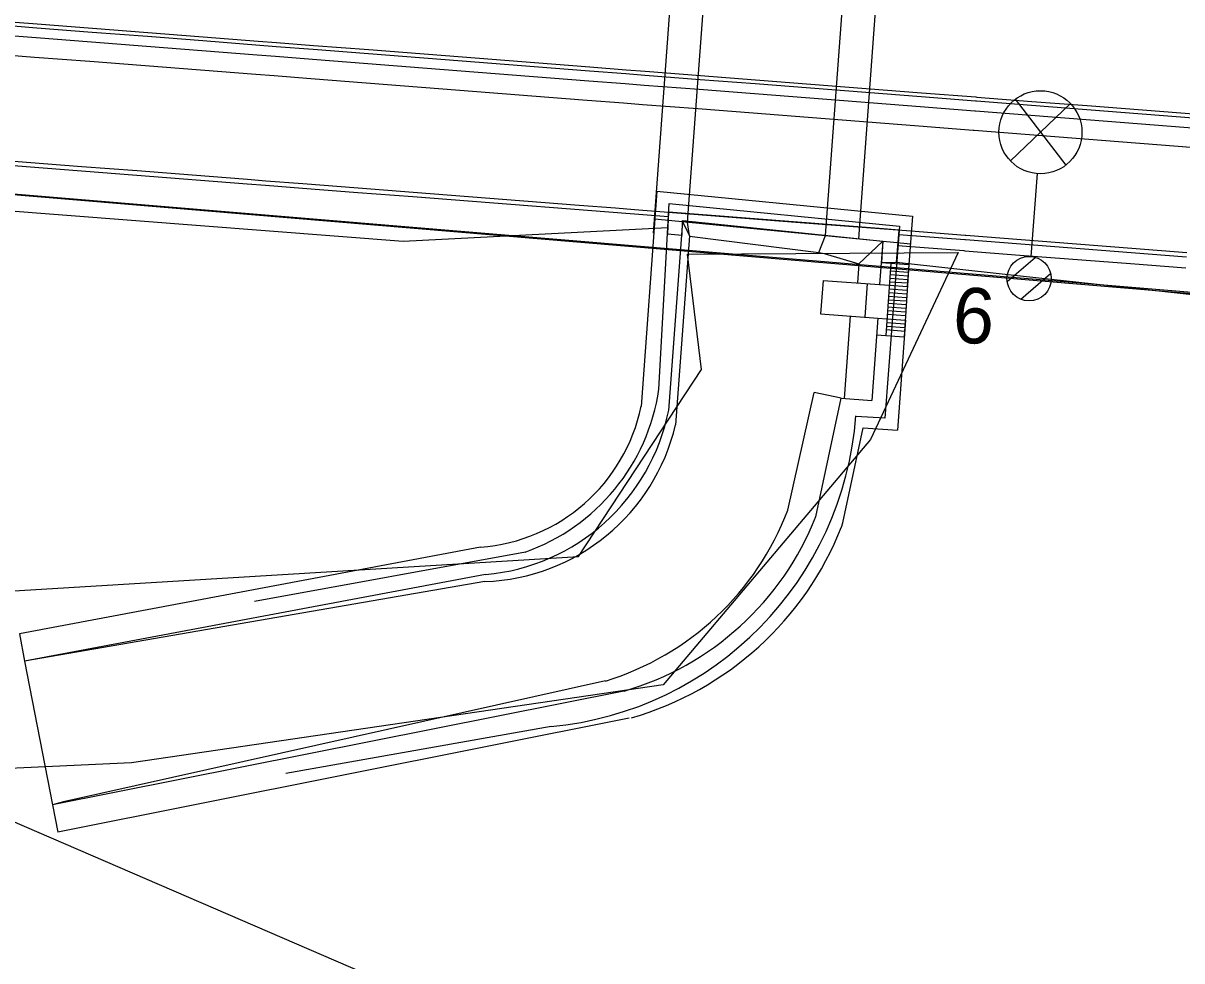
# Model space of a CAD drawing. Extents: x -670359 to -668019, y -978807 to -976674.
# Drawn here: x -669486.95 to -669466.04, y -977163.16 to -977146.25 of the extents above; entities that cross this region are included whole.
import ezdxf

# ---------------------------------------------------------------- set-up
doc = ezdxf.new("R2010")
doc.units = 0
for name, color, linetype in [('SO 01-20-01', 7, 'Continuous'), ('SO 01-86-01', 7, 'Continuous'), ('SO 11-12-01', 7, 'Continuous'), ('Vnitřní kresba', 7, 'Continuous')]:
    doc.layers.add(name, color=color, linetype=linetype)

# ---------------------------------------------------------------- blocks, each defined once
blk = doc.blocks.new('POINT_DISPLAY')
blk.add_line((0, 0), (0, 0))

msp = doc.modelspace()

# ---------------------------------------------------------------- linework, layer by layer
at = {"layer": 'SO 01-20-01'}
for p, q in [((-669475.576, -977150.04), (-669474.546, -977136.022)), ((-669474.959, -977149.839), (-669473.947, -977136.066)), ((-669472.47, -977150.083), (-669471.452, -977136.221)), ((-669471.836, -977149.643), (-669470.854, -977136.265)), ((-669475.513, -977149.282), (-669475.799, -977153.166)), ((-669475.513, -977149.282), (-669470.904, -977149.735)), ((-669475.478, -977152.855), (-669475.294, -977149.507)), ((-669475.294, -977149.507), (-669471.139, -977149.914)), ((-669471.873, -977150.142), (-669471.836, -977149.643)), ((-669475.55, -977149.781), (-669470.941, -977150.233)), ((-669475.051, -977149.83), (-669475.302, -977153.236)), ((-669475.051, -977149.83), (-669474.928, -977150.089)), ((-669474.928, -977150.089), (-669474.959, -977149.839)), ((-669471.139, -977149.914), (-669471.404, -977153.375)), ((-669470.904, -977149.735), (-669470.998, -977151.003)), ((-669474.928, -977150.089), (-669475.179, -977153.495)), ((-669474.928, -977150.092), (-669472.589, -977150.39)), ((-669472.589, -977150.39), (-669472.47, -977150.083)), ((-669471.87, -977150.593), (-669471.439, -977150.187)), ((-669471.439, -977150.187), (-669471.496, -977150.966)), ((-669472.589, -977150.39), (-669472.494, -977150.405)), ((-669472.494, -977150.405), (-669471.87, -977150.593)), ((-669471.87, -977150.593), (-669471.895, -977150.937)), ((-669471.467, -977150.568), (-669470.968, -977150.604)), ((-669471.29, -977150.581), (-669471.386, -977151.884)), ((-669471.3, -977150.72), (-669470.979, -977150.744)), ((-669471.295, -977150.655), (-669470.974, -977150.679)), ((-669470.968, -977150.604), (-669471.05, -977151.909)), ((-669472.516, -977150.892), (-669472.561, -977151.497)), ((-669472.516, -977150.892), (-669471.496, -977150.966)), ((-669471.718, -977150.95), (-669471.763, -977151.555)), ((-669471.496, -977150.966), (-669471.319, -977150.979)), ((-669471.315, -977150.915), (-669470.993, -977150.938)), ((-669471.31, -977150.85), (-669470.988, -977150.873)), ((-669471.305, -977150.785), (-669470.983, -977150.809)), ((-669471.334, -977151.174), (-669471.012, -977151.198)), ((-669471.329, -977151.109), (-669471.007, -977151.133)), ((-669471.324, -977151.044), (-669471.002, -977151.068)), ((-669471.319, -977150.979), (-669470.998, -977151.003)), ((-669471.348, -977151.368), (-669471.026, -977151.392)), ((-669471.343, -977151.304), (-669471.021, -977151.327)), ((-669471.338, -977151.239), (-669471.017, -977151.262)), ((-669472.561, -977151.497), (-669471.527, -977151.573)), ((-669472.026, -977151.536), (-669472.135, -977153.021)), ((-669471.527, -977151.573), (-669471.636, -977153.058)), ((-669471.527, -977151.573), (-669471.364, -977151.585)), ((-669471.364, -977151.585), (-669471.028, -977151.609)), ((-669471.357, -977151.498), (-669471.036, -977151.522)), ((-669471.353, -977151.433), (-669471.031, -977151.457)), ((-669471.378, -977151.779), (-669471.043, -977151.804)), ((-669471.373, -977151.714), (-669471.038, -977151.739)), ((-669471.369, -977151.65), (-669471.033, -977151.674)), ((-669471.028, -977151.609), (-669471.174, -977153.593)), ((-669471.549, -977151.872), (-669471.05, -977151.909)), ((-669473.152, -977155.031), (-669472.678, -977152.912)), ((-669472.189, -977153.017), (-669472.678, -977152.912)), ((-669472.649, -977155.155), (-669472.189, -977153.017)), ((-669472.189, -977153.017), (-669471.636, -977153.058)), ((-669471.404, -977153.375), (-669471.925, -977153.343)), ((-669472.16, -977155.261), (-669471.792, -977153.548)), ((-669471.792, -977153.548), (-669471.174, -977153.593)), ((-669472.184, -977155.34), (-669472.16, -977155.261)), ((-669478.697, -977155.702), (-669487.016, -977157.264)), ((-669482.773, -977156.673), (-669477.887, -977155.788)), ((-669478.605, -977156.193), (-669486.924, -977157.755)), ((-669478.615, -977156.322), (-669486.924, -977157.755)), ((-669487.016, -977157.264), (-669486.924, -977157.755)), ((-669486.924, -977157.755), (-669486.42, -977160.347)), ((-669476.439, -977158.113), (-669486.218, -977160.292)), ((-669476.109, -977158.295), (-669486.42, -977160.347)), ((-669476.011, -977158.785), (-669486.323, -977160.837)), ((-669477.419, -977158.934), (-669482.209, -977159.783)), ((-669486.218, -977160.292), (-669486.42, -977160.347)), ((-669486.42, -977160.347), (-669486.323, -977160.837))]:
    msp.add_line(p, q, dxfattribs=at)
for centre, radius, start, end in [((-669478.939, -977152.5), 3.211, 274.3323, 348.1321), ((-669478.933, -977152.504), 3.704, 275.1074, 348.7282), ((-669478.75, -977152.656), 3.669, 272.0762, 346.7766), ((-669477.574, -977153.204), 5.298, 286.0891, 338.4449), ((-669477.574, -977153.204), 5.798, 286.0404, 338.4235)]:
    msp.add_arc(centre, radius, start, end, dxfattribs=at)
for centre, major_axis, ratio, start_param, end_param in [((-669479.113, -977152.324), (-0.268, 3.665), 0.999859, 3.40753, 4.494824), ((-669477.988, -977152.881), (5.162, -3.214), 0.99986, 5.361213, 6.765491), ((-669478.008, -977153.148), (3.646, -3.732), 0.9906, 5.811258, 6.713935)]:
    msp.add_ellipse(centre, major_axis=major_axis, ratio=ratio, start_param=start_param, end_param=end_param, dxfattribs=at)
at = {"layer": 'SO 01-86-01'}
for p, q in [((-669445.341, -977152.857), (-669517.763, -977146.78)), ((-669445.341, -977152.857), (-669517.763, -977146.78)), ((-669443.485, -977152.976), (-669517.763, -977146.78)), ((-669469.049, -977147.626), (-669468.137, -977148.813)), ((-669469.135, -977148.736), (-669468.05, -977147.704)), ((-669468.651, -977148.966), (-669468.767, -977150.462)), ((-669469.192, -977150.91), (-669468.689, -977150.479)), ((-669468.948, -977151.227), (-669468.411, -977150.767))]:
    msp.add_line(p, q, dxfattribs=at)
for centre, radius in [((-669468.593, -977148.22), 0.749), ((-669468.798, -977150.86), 0.4)]:
    msp.add_circle(centre, radius, dxfattribs=at)
at = {"layer": 'SO 11-12-01'}
for p, q in [((-669487.696, -977146.258), (-669486.699, -977146.335)), ((-669487.69, -977146.188), (-669486.693, -977146.266)), ((-669486.699, -977146.335), (-669485.702, -977146.413)), ((-669486.693, -977146.266), (-669485.696, -977146.343)), ((-669485.696, -977146.343), (-669484.699, -977146.421)), ((-669487.71, -977146.437), (-669486.713, -977146.515)), ((-669486.713, -977146.515), (-669485.716, -977146.593)), ((-669485.702, -977146.413), (-669484.705, -977146.491)), ((-669484.705, -977146.491), (-669483.708, -977146.568)), ((-669484.699, -977146.421), (-669483.702, -977146.498)), ((-669483.708, -977146.568), (-669482.38, -977146.672)), ((-669483.702, -977146.498), (-669482.705, -977146.576)), ((-669482.705, -977146.576), (-669482.374, -977146.602)), ((-669487.737, -977146.786), (-669486.74, -977146.864)), ((-669485.716, -977146.593), (-669484.719, -977146.67)), ((-669484.719, -977146.67), (-669483.722, -977146.748)), ((-669483.722, -977146.748), (-669482.725, -977146.825)), ((-669482.38, -977146.672), (-669481.714, -977146.723)), ((-669482.374, -977146.602), (-669481.708, -977146.654)), ((-669481.714, -977146.723), (-669480.717, -977146.801)), ((-669481.708, -977146.654), (-669480.711, -977146.731)), ((-669480.711, -977146.731), (-669479.714, -977146.809)), ((-669486.74, -977146.864), (-669485.743, -977146.941)), ((-669485.743, -977146.941), (-669484.746, -977147.019)), ((-669482.725, -977146.825), (-669482.394, -977146.851)), ((-669482.394, -977146.851), (-669481.728, -977146.903)), ((-669481.728, -977146.903), (-669480.731, -977146.981)), ((-669480.731, -977146.981), (-669479.734, -977147.058)), ((-669480.717, -977146.801), (-669479.72, -977146.879)), ((-669479.72, -977146.879), (-669478.723, -977146.956)), ((-669479.714, -977146.809), (-669478.717, -977146.887)), ((-669478.723, -977146.956), (-669477.726, -977147.034)), ((-669478.717, -977146.887), (-669477.72, -977146.964)), ((-669477.72, -977146.964), (-669476.723, -977147.042)), ((-669484.746, -977147.019), (-669483.749, -977147.097)), ((-669483.749, -977147.097), (-669482.752, -977147.174)), ((-669482.752, -977147.174), (-669482.421, -977147.2)), ((-669482.421, -977147.2), (-669481.755, -977147.252)), ((-669479.734, -977147.058), (-669478.737, -977147.136)), ((-669478.737, -977147.136), (-669477.74, -977147.213)), ((-669477.726, -977147.034), (-669476.729, -977147.112)), ((-669476.729, -977147.112), (-669476.073, -977147.163)), ((-669476.723, -977147.042), (-669476.067, -977147.093)), ((-669476.073, -977147.163), (-669475.732, -977147.189)), ((-669476.067, -977147.093), (-669475.726, -977147.119)), ((-669475.732, -977147.189), (-669474.735, -977147.267)), ((-669475.726, -977147.119), (-669474.729, -977147.197)), ((-669474.729, -977147.197), (-669473.732, -977147.275)), ((-669481.755, -977147.252), (-669480.758, -977147.329)), ((-669480.758, -977147.329), (-669479.761, -977147.407)), ((-669479.761, -977147.407), (-669478.764, -977147.485)), ((-669477.74, -977147.213), (-669476.743, -977147.291)), ((-669476.743, -977147.291), (-669476.087, -977147.342)), ((-669476.087, -977147.342), (-669475.746, -977147.369)), ((-669475.746, -977147.369), (-669474.749, -977147.446)), ((-669474.735, -977147.267), (-669473.738, -977147.344)), ((-669473.738, -977147.344), (-669472.741, -977147.422)), ((-669473.732, -977147.275), (-669472.735, -977147.352)), ((-669472.735, -977147.352), (-669470.741, -977147.507)), ((-669478.764, -977147.485), (-669477.767, -977147.562)), ((-669477.767, -977147.562), (-669476.77, -977147.64)), ((-669474.749, -977147.446), (-669473.752, -977147.524)), ((-669473.752, -977147.524), (-669472.755, -977147.601)), ((-669472.755, -977147.601), (-669470.761, -977147.757)), ((-669472.741, -977147.422), (-669470.747, -977147.577)), ((-669470.747, -977147.577), (-669469.766, -977147.654)), ((-669470.741, -977147.507), (-669469.76, -977147.584)), ((-669469.76, -977147.584), (-669469.744, -977147.585)), ((-669469.744, -977147.585), (-669468.747, -977147.663)), ((-669476.77, -977147.64), (-669476.114, -977147.691)), ((-669476.114, -977147.691), (-669475.773, -977147.718)), ((-669475.773, -977147.718), (-669474.776, -977147.795)), ((-669474.776, -977147.795), (-669473.779, -977147.873)), ((-669470.761, -977147.757), (-669469.78, -977147.833)), ((-669469.78, -977147.833), (-669469.764, -977147.834)), ((-669469.766, -977147.654), (-669469.75, -977147.655)), ((-669469.764, -977147.834), (-669468.767, -977147.912)), ((-669469.75, -977147.655), (-669468.753, -977147.732)), ((-669468.753, -977147.732), (-669467.756, -977147.81)), ((-669468.747, -977147.663), (-669467.75, -977147.74)), ((-669467.756, -977147.81), (-669466.759, -977147.888)), ((-669467.75, -977147.74), (-669466.753, -977147.818)), ((-669466.753, -977147.818), (-669465.756, -977147.895)), ((-669473.779, -977147.873), (-669472.782, -977147.95)), ((-669472.782, -977147.95), (-669470.788, -977148.106)), ((-669468.767, -977147.912), (-669467.77, -977147.989)), ((-669467.77, -977147.989), (-669466.773, -977148.067)), ((-669466.759, -977147.888), (-669465.762, -977147.965)), ((-669470.788, -977148.106), (-669469.807, -977148.182)), ((-669469.807, -977148.182), (-669469.791, -977148.183)), ((-669469.791, -977148.183), (-669468.794, -977148.261)), ((-669466.773, -977148.067), (-669465.776, -977148.145)), ((-669468.794, -977148.261), (-669467.797, -977148.338)), ((-669467.797, -977148.338), (-669466.8, -977148.416)), ((-669466.8, -977148.416), (-669465.803, -977148.494)), ((-669497.465, -977148.84), (-669480.094, -977150.182)), ((-669487.89, -977148.76), (-669486.893, -977148.838)), ((-669487.884, -977148.681), (-669486.887, -977148.758)), ((-669486.893, -977148.838), (-669485.896, -977148.915)), ((-669486.887, -977148.758), (-669485.89, -977148.836)), ((-669485.89, -977148.836), (-669484.893, -977148.913)), ((-669485.896, -977148.915), (-669484.899, -977148.993)), ((-669484.899, -977148.993), (-669482.905, -977149.148)), ((-669484.893, -977148.913), (-669483.896, -977148.991)), ((-669483.896, -977148.991), (-669482.899, -977149.069)), ((-669482.899, -977149.069), (-669482.568, -977149.094)), ((-669482.905, -977149.148), (-669482.574, -977149.174)), ((-669482.574, -977149.174), (-669481.908, -977149.226)), ((-669482.568, -977149.094), (-669481.902, -977149.146)), ((-669481.908, -977149.226), (-669480.911, -977149.304)), ((-669481.902, -977149.146), (-669480.905, -977149.224)), ((-669480.905, -977149.224), (-669479.908, -977149.301)), ((-669479.908, -977149.301), (-669478.911, -977149.379)), ((-669480.911, -977149.304), (-669479.914, -977149.381)), ((-669479.914, -977149.381), (-669475.307, -977149.74)), ((-669478.911, -977149.379), (-669477.914, -977149.457)), ((-669477.914, -977149.457), (-669476.917, -977149.534)), ((-669476.917, -977149.534), (-669476.261, -977149.585)), ((-669476.261, -977149.585), (-669475.92, -977149.612)), ((-669475.92, -977149.612), (-669474.923, -977149.689)), ((-669475.302, -977149.66), (-669475.309, -977149.787)), ((-669471.425, -977149.962), (-669475.302, -977149.66)), ((-669474.923, -977149.689), (-669473.926, -977149.767)), ((-669475.309, -977149.787), (-669475.324, -977150.051)), ((-669475.059, -977150.075), (-669475.051, -977149.814)), ((-669475.051, -977149.814), (-669471.439, -977150.187)), ((-669473.926, -977149.767), (-669472.929, -977149.845)), ((-669472.929, -977149.845), (-669470.935, -977150)), ((-669480.094, -977150.182), (-669475.318, -977149.94)), ((-669475.324, -977150.051), (-669475.059, -977150.075)), ((-669471.144, -977149.984), (-669471.425, -977149.962)), ((-669471.189, -977150.565), (-669471.144, -977149.984)), ((-669471.15, -977150.063), (-669469.96, -977150.156)), ((-669470.935, -977150), (-669469.954, -977150.076)), ((-669469.954, -977150.076), (-669469.938, -977150.077)), ((-669469.938, -977150.077), (-669468.941, -977150.155)), ((-669471.439, -977150.187), (-669471.462, -977150.568)), ((-669471.166, -977150.263), (-669469.976, -977150.355)), ((-669471.166, -977150.263), (-669469.976, -977150.355)), ((-669469.96, -977150.156), (-669469.945, -977150.157)), ((-669469.945, -977150.157), (-669468.948, -977150.235)), ((-669468.948, -977150.235), (-669466.954, -977150.39)), ((-669468.941, -977150.155), (-669467.944, -977150.233)), ((-669467.944, -977150.233), (-669466.947, -977150.31)), ((-669466.947, -977150.31), (-669465.951, -977150.388)), ((-669469.976, -977150.355), (-669469.96, -977150.357)), ((-669469.976, -977150.355), (-669469.96, -977150.357)), ((-669469.96, -977150.357), (-669468.963, -977150.434)), ((-669469.96, -977150.357), (-669468.963, -977150.434)), ((-669468.963, -977150.434), (-669466.969, -977150.589)), ((-669468.963, -977150.434), (-669466.969, -977150.589)), ((-669466.954, -977150.39), (-669465.957, -977150.468)), ((-669471.462, -977150.568), (-669471.189, -977150.565)), ((-669471.189, -977150.565), (-669469.174, -977150.785)), ((-669466.969, -977150.589), (-669465.972, -977150.667)), ((-669466.969, -977150.589), (-669465.972, -977150.667)), ((-669469.174, -977150.785), (-669453.419, -977152.5))]:
    msp.add_line(p, q, dxfattribs=at)
at = {"layer": 'Vnitřní kresba'}
for points in [[(-669474.96, -977150.42), (-669470.08, -977150.39)], [(-669474.71, -977152.5), (-669474.96, -977150.42)], [(-669470.08, -977150.39), (-669471.66, -977153.76)], [(-669476.93, -977155.87), (-669474.71, -977152.5)], [(-669471.66, -977153.76), (-669475.4, -977158.18)], [(-669488.6, -977156.58), (-669476.93, -977155.87)], [(-669475.4, -977158.18), (-669484.99, -977159.59)], [(-669484.99, -977159.59), (-669489.14, -977159.78)], [(-669472.71, -977166.87), (-669489.14, -977159.78)]]:
    msp.add_lwpolyline(points, dxfattribs=at)

# ---------------------------------------------------------------- block references
at = {"layer": 'SO 01-86-01', "rotation": -4.450857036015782}
msp.add_blockref('POINT_DISPLAY', (-669468.798, -977150.86), dxfattribs=at)

# ---------------------------------------------------------------- texts
at = {"layer": 'SO 01-86-01'}
msp.add_text('6', height=1, rotation=356.1, dxfattribs=at).set_placement((-669470.2, -977152))

doc.saveas('drawing.dxf')
